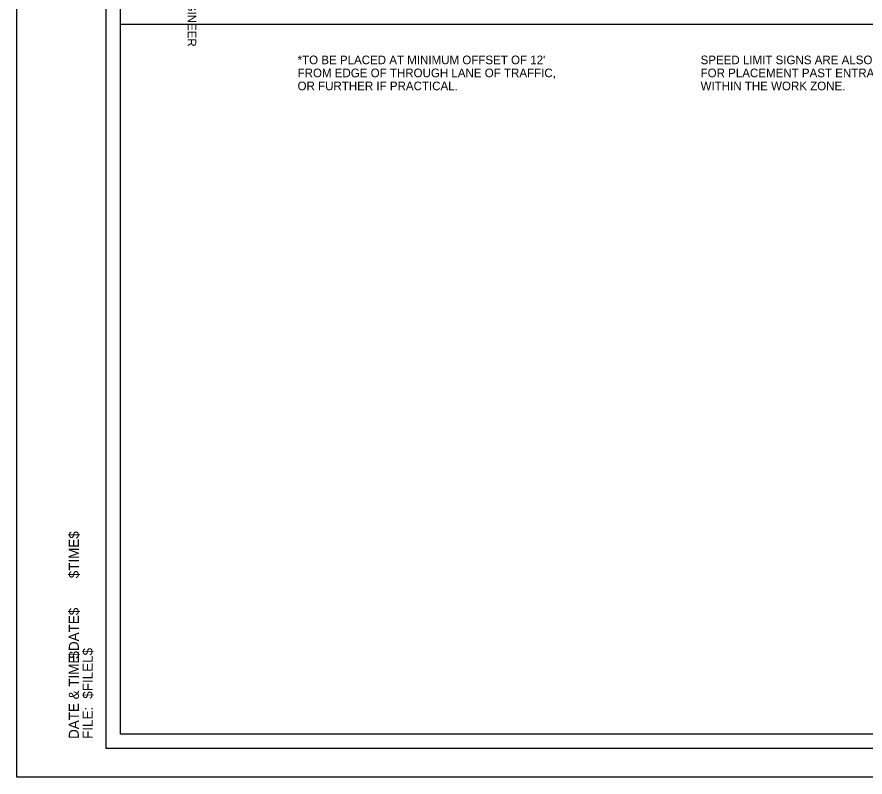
# Model space of a CAD drawing. Extents: x 1373222 to 1374279, y 380783 to 380996.
# Drawn here: x 1373583.7 to 1373701.6, y 380783.1 to 380888.9 of the extents above; entities that cross this region are included whole.
import ezdxf

# ---------------------------------------------------------------- set-up
doc = ezdxf.new("R2010")
doc.units = 0
for name, color, linetype in [('Default', 7, 'Continuous'), ('R_Border', 7, 'Continuous'), ('R_Border Notes', 7, 'Continuous'), ('R_No Plot', 7, 'Continuous')]:
    doc.layers.add(name, color=color, linetype=linetype)

msp = doc.modelspace()

# ---------------------------------------------------------------- linework, layer by layer
at = {"layer": 'R_Border'}
for p, q in [((1373596.1, 380787.13), (1373596.1, 380992.59)), ((1373596.1, 380787.13), (1373596.1, 380787.13)), ((1373912.28, 380787.13), (1373596.1, 380787.13))]:
    msp.add_line(p, q, dxfattribs=at)
at = {"layer": 'R_No Plot'}
for points in [[(1373583.69, 380996.49), (1373917.03, 380996.49), (1373917.03, 380783.15), (1373583.69, 380783.15)], [(1373598.1, 380990.59), (1373847.64, 380990.59), (1373847.64, 380980.71), (1373865.18, 380980.71), (1373889.28, 380980.71), (1373889.28, 380958.38), (1373910.28, 380958.38), (1373910.28, 380789.13), (1373598.1, 380789.13)], [(1373598.1, 380887.86), (1373910.28, 380887.86), (1373910.28, 380789.13), (1373598.1, 380789.13)]]:
    msp.add_lwpolyline(points, close=True, dxfattribs=at)

# ---------------------------------------------------------------- texts
at = {"layer": 'Default'}
for s, rotation, p in [('TO BE USED IF AND WHERE DIRECTED BY THE ENGINEER', 270, (1373607.42, 380930.28)), ("*TO BE PLACED AT MINIMUM OFFSET OF 12'", 360, (1373622.72, 380882.29)), ('FROM EDGE OF THROUGH LANE OF TRAFFIC,', 360, (1373622.72, 380880.48)), ('OR FURTHER IF PRACTICAL.', 360, (1373622.72, 380878.67))]:
    msp.add_text(s, height=1.2, rotation=rotation, dxfattribs=at).set_placement(p)
for s, p in [('SPEED LIMIT SIGNS ARE ALSO PROVIDED', (1373678.77, 380882.29)), ('FOR PLACEMENT PAST ENTRANCE RAMPS ', (1373678.77, 380880.48)), ('WITHIN THE WORK ZONE.', (1373678.77, 380878.67))]:
    msp.add_text(s, height=1.2, dxfattribs=at).set_placement(p)
at = {"layer": 'R_Border Notes'}
for s, height, p in [('$TIME$', 1.397, (1373592.3, 380810.8)), ('$DATE$', 1.397, (1373592.3, 380799.63)), ('DATE & TIME:', 1.3968, (1373592.3, 380788.45)), ('$FILEL$', 1.397, (1373594.22, 380794.04)), ('FILE: ', 1.397, (1373594.22, 380788.45))]:
    msp.add_text(s, height=height, rotation=90, dxfattribs=at).set_placement(p)

doc.saveas('drawing.dxf')
